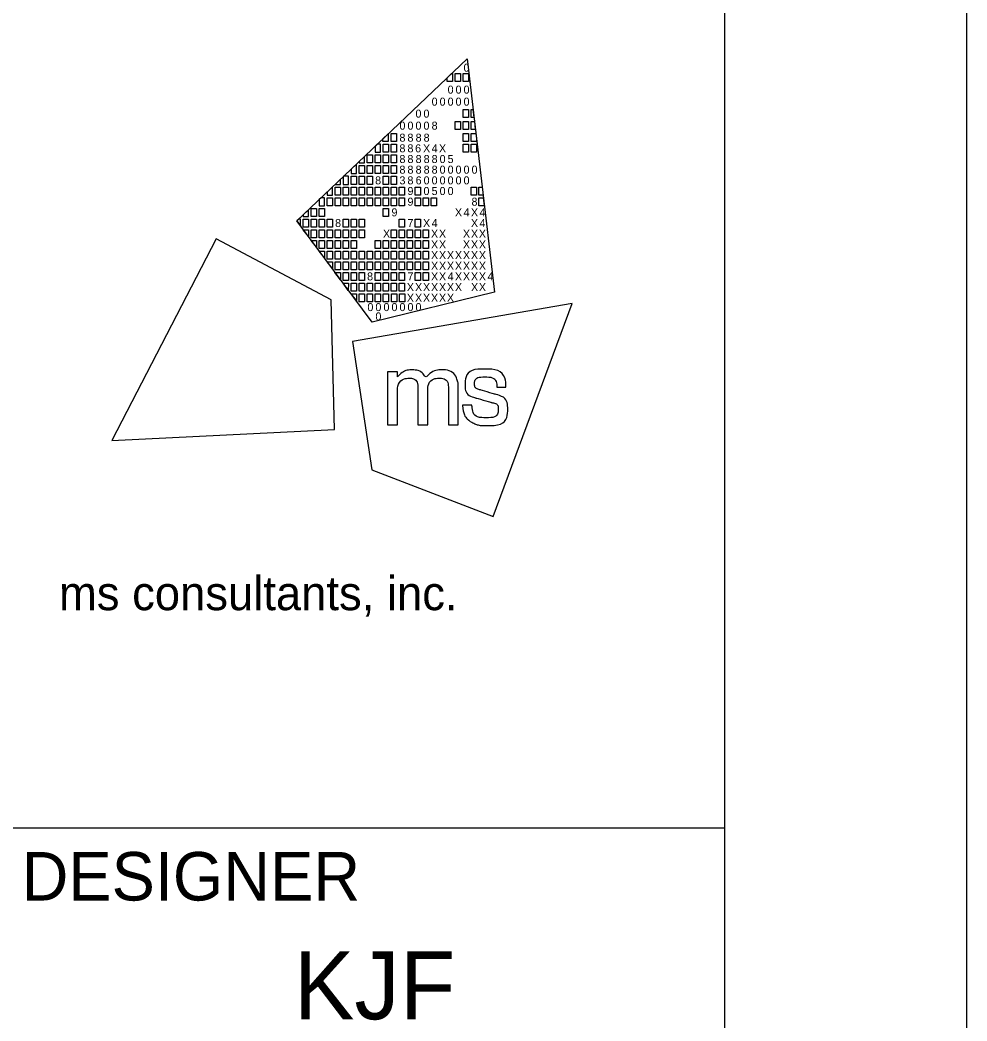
# Model space of a CAD drawing. Extents: x 0 to 40.3, y -1.2 to 22.
# Drawn here: x 32.047 to 34, y 2.102 to 4.166 of the extents above; entities that cross this region are included whole.
import ezdxf

# ---------------------------------------------------------------- set-up
doc = ezdxf.new("R2010")
doc.units = 0
for name, color, linetype in [('SH_Border', 7, 'Continuous'), ('SH_Cut_Line', 7, 'Continuous'), ('SH_Data', 7, 'Continuous')]:
    doc.layers.add(name, color=color, linetype=linetype)

msp = doc.modelspace()

# ---------------------------------------------------------------- linework, layer by layer
at = {"layer": 'SH_Border'}
for p, q in [((32.6175, 3.7519), (32.9688, 4.0861)), ((32.9688, 4.0861), (32.9688, 4.0861)), ((32.9688, 4.0861), (33.0253, 3.6052)), ((32.773, 3.543), (32.6175, 3.7519)), ((33.0253, 3.6052), (32.773, 3.543)), ((32, 2.5), (33.5, 2.5))]:
    msp.add_line(p, q, dxfattribs=at)
for points in [[(1.5, 21.5), (33.5, 21.5), (33.5, 0.5), (1.5, 0.5)], [(32.9279, 4.0472), (32.9369, 4.0558), (32.9389, 4.0558), (32.9389, 4.0393), (32.9279, 4.0393)], [(32.9444, 4.0558), (32.9554, 4.0558), (32.9554, 4.0393), (32.9444, 4.0393)], [(32.9609, 4.0558), (32.9719, 4.0558), (32.9719, 4.0393), (32.9609, 4.0393)], [(32.9606, 3.9815), (32.9716, 3.9815), (32.9716, 3.965), (32.9606, 3.965)], [(32.9771, 3.9815), (32.9811, 3.9815), (32.983, 3.965), (32.9771, 3.965)], [(32.9441, 3.9567), (32.9551, 3.9567), (32.9551, 3.9402), (32.9441, 3.9402)], [(32.9606, 3.9567), (32.9716, 3.9567), (32.9716, 3.9402), (32.9606, 3.9402)], [(32.9771, 3.9567), (32.984, 3.9567), (32.9859, 3.9402), (32.9771, 3.9402)], [(32.7953, 3.9211), (32.8064, 3.9316), (32.8064, 3.9154), (32.7953, 3.9154)], [(32.8123, 3.9319), (32.8233, 3.9319), (32.8233, 3.9154), (32.8123, 3.9154)], [(32.9606, 3.9319), (32.9716, 3.9319), (32.9716, 3.9154), (32.9606, 3.9154)], [(32.9771, 3.9319), (32.9869, 3.9319), (32.9881, 3.9218), (32.9881, 3.9154), (32.9771, 3.9154)], [(32.7958, 3.9099), (32.8068, 3.9099), (32.8068, 3.8934), (32.7958, 3.8934)], [(32.8123, 3.9099), (32.8233, 3.9099), (32.8233, 3.8934), (32.8123, 3.8934)], [(32.9606, 3.9099), (32.9716, 3.9099), (32.9716, 3.8934), (32.9606, 3.8934)], [(32.9771, 3.9099), (32.9881, 3.9099), (32.9881, 3.8934), (32.9771, 3.8934)], [(32.7627, 3.8879), (32.7737, 3.8879), (32.7737, 3.8714), (32.7627, 3.8714)], [(32.7793, 3.8879), (32.7903, 3.8879), (32.7903, 3.8714), (32.7793, 3.8714)], [(32.7958, 3.8879), (32.8068, 3.8879), (32.8068, 3.8714), (32.7958, 3.8714)], [(32.8123, 3.8879), (32.8233, 3.8879), (32.8233, 3.8714), (32.8123, 3.8714)], [(32.7462, 3.8659), (32.7572, 3.8659), (32.7572, 3.8494), (32.7462, 3.8494)], [(32.7627, 3.8659), (32.7737, 3.8659), (32.7737, 3.8494), (32.7627, 3.8494)], [(32.7793, 3.8659), (32.7903, 3.8659), (32.7903, 3.8494), (32.7793, 3.8494)], [(32.7958, 3.8659), (32.8068, 3.8659), (32.8068, 3.8494), (32.7958, 3.8494)], [(32.8123, 3.8659), (32.8233, 3.8659), (32.8233, 3.8494), (32.8123, 3.8494)], [(32.7297, 3.8439), (32.7407, 3.8439), (32.7407, 3.8273), (32.7297, 3.8273)], [(32.7462, 3.8439), (32.7572, 3.8439), (32.7572, 3.8273), (32.7462, 3.8273)], [(32.7627, 3.8439), (32.7737, 3.8439), (32.7737, 3.8273), (32.7627, 3.8273)], [(32.7958, 3.8439), (32.8068, 3.8439), (32.8068, 3.8273), (32.7958, 3.8273)], [(32.8123, 3.8439), (32.8233, 3.8439), (32.8233, 3.8273), (32.8123, 3.8273)], [(32.6967, 3.8218), (32.7077, 3.8218), (32.7077, 3.8053), (32.6967, 3.8053)], [(32.7132, 3.8218), (32.7242, 3.8218), (32.7242, 3.8053), (32.7132, 3.8053)], [(32.7297, 3.8218), (32.7407, 3.8218), (32.7407, 3.8053), (32.7297, 3.8053)], [(32.7462, 3.8218), (32.7572, 3.8218), (32.7572, 3.8053), (32.7462, 3.8053)], [(32.7627, 3.8218), (32.7737, 3.8218), (32.7737, 3.8053), (32.7627, 3.8053)], [(32.7793, 3.8218), (32.7903, 3.8218), (32.7903, 3.8053), (32.7793, 3.8053)], [(32.7958, 3.8218), (32.8068, 3.8218), (32.8068, 3.8053), (32.7958, 3.8053)], [(32.8123, 3.8218), (32.8233, 3.8218), (32.8233, 3.8053), (32.8123, 3.8053)], [(32.8288, 3.8218), (32.8398, 3.8218), (32.8398, 3.8053), (32.8288, 3.8053)], [(32.8618, 3.8218), (32.8728, 3.8218), (32.8728, 3.8053), (32.8618, 3.8053)], [(32.9771, 3.8218), (32.9881, 3.8218), (32.9881, 3.8053), (32.9771, 3.8053)], [(32.9935, 3.8218), (32.9998, 3.8218), (33.0018, 3.8053), (32.9935, 3.8053)], [(32.6802, 3.7998), (32.6912, 3.7998), (32.6912, 3.7833), (32.6802, 3.7833)], [(32.6967, 3.7998), (32.7077, 3.7998), (32.7077, 3.7833), (32.6967, 3.7833)], [(32.7132, 3.7998), (32.7242, 3.7998), (32.7242, 3.7833), (32.7132, 3.7833)], [(32.7297, 3.7998), (32.7407, 3.7998), (32.7407, 3.7833), (32.7297, 3.7833)], [(32.7462, 3.7998), (32.7572, 3.7998), (32.7572, 3.7833), (32.7462, 3.7833)], [(32.7627, 3.7998), (32.7737, 3.7998), (32.7737, 3.7833), (32.7627, 3.7833)], [(32.7793, 3.7998), (32.7903, 3.7998), (32.7903, 3.7833), (32.7793, 3.7833)], [(32.7958, 3.7998), (32.8068, 3.7998), (32.8068, 3.7833), (32.7958, 3.7833)], [(32.8123, 3.7998), (32.8233, 3.7998), (32.8233, 3.7833), (32.8123, 3.7833)], [(32.8288, 3.7998), (32.8398, 3.7998), (32.8398, 3.7833), (32.8288, 3.7833)], [(32.8618, 3.7998), (32.8728, 3.7998), (32.8728, 3.7833), (32.8618, 3.7833)], [(32.8783, 3.7998), (32.8893, 3.7998), (32.8893, 3.7833), (32.8783, 3.7833)], [(32.8947, 3.7998), (32.9057, 3.7998), (32.9057, 3.7833), (32.8947, 3.7833)], [(32.9935, 3.7998), (33.0024, 3.7998), (33.0044, 3.7833), (32.9935, 3.7833)], [(32.6471, 3.7778), (32.6581, 3.7778), (32.6581, 3.7613), (32.6471, 3.7613)], [(32.6637, 3.7778), (32.6747, 3.7778), (32.6747, 3.7613), (32.6637, 3.7613)], [(32.7958, 3.7778), (32.8068, 3.7778), (32.8068, 3.7613), (32.7958, 3.7613)], [(32.6306, 3.7558), (32.6416, 3.7558), (32.6416, 3.7393), (32.6306, 3.7393)], [(32.6471, 3.7558), (32.6581, 3.7558), (32.6581, 3.7393), (32.6471, 3.7393)], [(32.6637, 3.7558), (32.6747, 3.7558), (32.6747, 3.7393), (32.6637, 3.7393)], [(32.6802, 3.7558), (32.6912, 3.7558), (32.6912, 3.7393), (32.6802, 3.7393)], [(32.7132, 3.7558), (32.7242, 3.7558), (32.7242, 3.7393), (32.7132, 3.7393)], [(32.7297, 3.7558), (32.7407, 3.7558), (32.7407, 3.7393), (32.7297, 3.7393)], [(32.7462, 3.7558), (32.7572, 3.7558), (32.7572, 3.7393), (32.7462, 3.7393)], [(32.8288, 3.7558), (32.8398, 3.7558), (32.8398, 3.7393), (32.8288, 3.7393)], [(32.8618, 3.7558), (32.8728, 3.7558), (32.8728, 3.7393), (32.8618, 3.7393)], [(32.6306, 3.7338), (32.6416, 3.7338), (32.6416, 3.72)], [(32.6471, 3.7338), (32.6581, 3.7338), (32.6581, 3.7173), (32.6471, 3.7173)], [(32.6637, 3.7338), (32.6747, 3.7338), (32.6747, 3.7173), (32.6637, 3.7173)], [(32.6802, 3.7338), (32.6912, 3.7338), (32.6912, 3.7173), (32.6802, 3.7173)], [(32.6967, 3.7338), (32.7077, 3.7338), (32.7077, 3.7173), (32.6967, 3.7173)], [(32.7132, 3.7338), (32.7242, 3.7338), (32.7242, 3.7173), (32.7132, 3.7173)], [(32.7297, 3.7338), (32.7407, 3.7338), (32.7407, 3.7173), (32.7297, 3.7173)], [(32.7462, 3.7338), (32.7572, 3.7338), (32.7572, 3.7173), (32.7462, 3.7173)], [(32.8123, 3.7338), (32.8233, 3.7338), (32.8233, 3.7173), (32.8123, 3.7173)], [(32.8288, 3.7338), (32.8398, 3.7338), (32.8398, 3.7173), (32.8288, 3.7173)], [(32.8453, 3.7338), (32.8563, 3.7338), (32.8563, 3.7173), (32.8453, 3.7173)], [(32.8618, 3.7338), (32.8728, 3.7338), (32.8728, 3.7173), (32.8618, 3.7173)], [(32.8783, 3.7338), (32.8893, 3.7338), (32.8893, 3.7173), (32.8783, 3.7173)], [(32.6471, 3.7117), (32.6581, 3.7117), (32.6581, 3.698)], [(32.6637, 3.7117), (32.6747, 3.7117), (32.6747, 3.6952), (32.6637, 3.6952)], [(32.6802, 3.7117), (32.6912, 3.7117), (32.6912, 3.6952), (32.6802, 3.6952)], [(32.6967, 3.7117), (32.7077, 3.7117), (32.7077, 3.6952), (32.6967, 3.6952)], [(32.7132, 3.7117), (32.7242, 3.7117), (32.7242, 3.6952), (32.7132, 3.6952)], [(32.7297, 3.7117), (32.7407, 3.7117), (32.7407, 3.6952), (32.7297, 3.6952)], [(32.7793, 3.7117), (32.7903, 3.7117), (32.7903, 3.6952), (32.7793, 3.6952)], [(32.7958, 3.7117), (32.8068, 3.7117), (32.8068, 3.6952), (32.7958, 3.6952)], [(32.8123, 3.7117), (32.8233, 3.7117), (32.8233, 3.6952), (32.8123, 3.6952)], [(32.8288, 3.7117), (32.8398, 3.7117), (32.8398, 3.6952), (32.8288, 3.6952)], [(32.8453, 3.7117), (32.8563, 3.7117), (32.8563, 3.6952), (32.8453, 3.6952)], [(32.8618, 3.7117), (32.8728, 3.7117), (32.8728, 3.6952), (32.8618, 3.6952)], [(32.8783, 3.7117), (32.8893, 3.7117), (32.8893, 3.6952), (32.8783, 3.6952)], [(32.6637, 3.6897), (32.6747, 3.6897), (32.6747, 3.676)], [(32.6747, 3.6897), (32.6747, 3.6897), (32.6747, 3.6897)], [(32.6802, 3.6897), (32.6912, 3.6897), (32.6912, 3.6732), (32.6802, 3.6732)], [(32.6967, 3.6897), (32.7077, 3.6897), (32.7077, 3.6732), (32.6967, 3.6732)], [(32.7132, 3.6897), (32.7242, 3.6897), (32.7242, 3.6732), (32.7132, 3.6732)], [(32.7297, 3.6897), (32.7407, 3.6897), (32.7407, 3.6732), (32.7297, 3.6732)], [(32.7462, 3.6897), (32.7572, 3.6897), (32.7572, 3.6732), (32.7462, 3.6732)], [(32.7627, 3.6897), (32.7737, 3.6897), (32.7737, 3.6732), (32.7627, 3.6732)], [(32.7793, 3.6897), (32.7903, 3.6897), (32.7903, 3.6732), (32.7793, 3.6732)], [(32.7958, 3.6897), (32.8068, 3.6897), (32.8068, 3.6732), (32.7958, 3.6732)], [(32.8123, 3.6897), (32.8233, 3.6897), (32.8233, 3.6732), (32.8123, 3.6732)], [(32.8288, 3.6897), (32.8398, 3.6897), (32.8398, 3.6732), (32.8288, 3.6732)], [(32.8453, 3.6897), (32.8563, 3.6897), (32.8563, 3.6732), (32.8453, 3.6732)], [(32.8618, 3.6897), (32.8728, 3.6897), (32.8728, 3.6732), (32.8618, 3.6732)], [(32.8783, 3.6897), (32.8893, 3.6897), (32.8893, 3.6732), (32.8783, 3.6732)], [(32.6802, 3.6677), (32.6912, 3.6677), (32.6912, 3.654)], [(32.6967, 3.6677), (32.7077, 3.6677), (32.7077, 3.6512), (32.6967, 3.6512)], [(32.7132, 3.6677), (32.7242, 3.6677), (32.7242, 3.6512), (32.7132, 3.6512)], [(32.7297, 3.6677), (32.7407, 3.6677), (32.7407, 3.6512), (32.7297, 3.6512)], [(32.7462, 3.6677), (32.7572, 3.6677), (32.7572, 3.6512), (32.7462, 3.6512)], [(32.7627, 3.6677), (32.7737, 3.6677), (32.7737, 3.6512), (32.7627, 3.6512)], [(32.7793, 3.6677), (32.7903, 3.6677), (32.7903, 3.6512), (32.7793, 3.6512)], [(32.7958, 3.6677), (32.8068, 3.6677), (32.8068, 3.6512), (32.7958, 3.6512)], [(32.8123, 3.6677), (32.8233, 3.6677), (32.8233, 3.6512), (32.8123, 3.6512)], [(32.8288, 3.6677), (32.8398, 3.6677), (32.8398, 3.6512), (32.8288, 3.6512)], [(32.8453, 3.6677), (32.8563, 3.6677), (32.8563, 3.6512), (32.8453, 3.6512)], [(32.8618, 3.6677), (32.8728, 3.6677), (32.8728, 3.6512), (32.8618, 3.6512)], [(32.8783, 3.6677), (32.8893, 3.6677), (32.8893, 3.6512), (32.8783, 3.6512)], [(32.7077, 3.6305), (32.6965, 3.6457), (32.7077, 3.6457)], [(32.7132, 3.6457), (32.7242, 3.6457), (32.7242, 3.6292), (32.7132, 3.6292)], [(32.7297, 3.6457), (32.7407, 3.6457), (32.7407, 3.6292), (32.7297, 3.6292)], [(32.7462, 3.6457), (32.7572, 3.6457), (32.7572, 3.6292), (32.7462, 3.6292)], [(32.7793, 3.6457), (32.7903, 3.6457), (32.7903, 3.6292), (32.7793, 3.6292)], [(32.7958, 3.6457), (32.8068, 3.6457), (32.8068, 3.6292), (32.7958, 3.6292)], [(32.8123, 3.6457), (32.8233, 3.6457), (32.8233, 3.6292), (32.8123, 3.6292)], [(32.8288, 3.6457), (32.8398, 3.6457), (32.8398, 3.6292), (32.8288, 3.6292)], [(32.8618, 3.6457), (32.8728, 3.6457), (32.8728, 3.6292), (32.8618, 3.6292)], [(32.8783, 3.6457), (32.8893, 3.6457), (32.8893, 3.6292), (32.8783, 3.6292)], [(32.724, 3.6082), (32.7132, 3.6237), (32.7242, 3.6237)], [(32.7297, 3.6237), (32.7407, 3.6237), (32.7407, 3.6072), (32.7297, 3.6072)], [(32.7462, 3.6237), (32.7572, 3.6237), (32.7572, 3.6072), (32.7462, 3.6072)], [(32.7627, 3.6237), (32.7737, 3.6237), (32.7737, 3.6072), (32.7627, 3.6072)], [(32.7793, 3.6237), (32.7903, 3.6237), (32.7903, 3.6072), (32.7793, 3.6072)], [(32.7958, 3.6237), (32.8068, 3.6237), (32.8068, 3.6072), (32.7958, 3.6072)], [(32.8123, 3.6237), (32.8233, 3.6237), (32.8233, 3.6072), (32.8123, 3.6072)], [(32.8288, 3.6237), (32.8398, 3.6237), (32.8398, 3.6072), (32.8288, 3.6072)], [(32.7302, 3.6017), (32.7407, 3.6017), (32.7408, 3.5875)], [(32.7463, 3.6017), (32.7573, 3.6017), (32.7573, 3.5852), (32.7463, 3.5852)], [(32.763, 3.6017), (32.774, 3.6017), (32.774, 3.5852), (32.763, 3.5852)], [(32.7794, 3.6017), (32.7904, 3.6017), (32.7904, 3.5852), (32.7794, 3.5852)], [(32.796, 3.6017), (32.807, 3.6017), (32.807, 3.5852), (32.796, 3.5852)], [(32.8129, 3.6017), (32.8239, 3.6017), (32.8239, 3.5851), (32.8129, 3.5851)], [(32.8296, 3.6017), (32.8406, 3.6017), (32.8406, 3.5851), (32.8296, 3.5851)]]:
    msp.add_lwpolyline(points, close=True, dxfattribs=at)
for points in [[(32.7903, 3.9099), (32.7836, 3.9099), (32.7793, 3.9058), (32.7793, 3.8934), (32.7903, 3.8934), (32.7903, 3.9099)], [(32.7572, 3.8849), (32.7462, 3.8744), (32.7462, 3.8714), (32.7572, 3.8714), (32.7572, 3.8849)], [(32.7407, 3.8691), (32.7297, 3.8587), (32.7297, 3.8494), (32.7407, 3.8494), (32.7407, 3.8691)], [(32.7242, 3.8439), (32.7141, 3.8439), (32.7132, 3.843), (32.7132, 3.8273), (32.7242, 3.8273), (32.7242, 3.8439)], [(32.6912, 3.822), (32.6802, 3.8115), (32.6802, 3.8053), (32.6912, 3.8053), (32.6912, 3.822)], [(32.7077, 3.8377), (32.6968, 3.8273), (32.7077, 3.8273), (32.7077, 3.8377)], [(32.6747, 3.7998), (32.6679, 3.7998), (32.6637, 3.7958), (32.6637, 3.7833), (32.6747, 3.7833), (32.6747, 3.7998)], [(32.6416, 3.7749), (32.6306, 3.7644), (32.6306, 3.7613), (32.6416, 3.7613), (32.6416, 3.7749)], [(32.6251, 3.7558), (32.6216, 3.7558), (32.6175, 3.7519), (32.6251, 3.7417), (32.6251, 3.7558)], [(32.4512, 3.7149), (32.2359, 3.2988), (32.6956, 3.3215), (32.6884, 3.5892), (32.4512, 3.7149)], [(33.0229, 3.1422), (33.1859, 3.5814), (32.7324, 3.5029), (32.7722, 3.2381), (33.0229, 3.1422)]]:
    msp.add_lwpolyline(points, dxfattribs=at)
for points in [[(32.8048, 3.3315), (32.8048, 3.3315), (32.8048, 3.4409), (32.8048, 3.4409), (32.8048, 3.4409), (32.8255, 3.4409), (32.8255, 3.4409), (32.8255, 3.4409), (32.8255, 3.4297), (32.8255, 3.4297), (32.8346, 3.4399), (32.8457, 3.4445), (32.8555, 3.4445), (32.8688, 3.4445), (32.8791, 3.4372), (32.8837, 3.4266), (32.8915, 3.4381), (32.905, 3.4446), (32.9166, 3.4446), (32.9325, 3.4446), (32.9451, 3.435), (32.9494, 3.4213), (32.9494, 3.4212), (32.9494, 3.4212), (32.9494, 3.4212), (32.9501, 3.419), (32.9506, 3.4172), (32.9506, 3.4071), (32.9506, 3.4071), (32.9506, 3.3314), (32.9506, 3.3314), (32.9506, 3.3314), (32.9303, 3.3314), (32.9303, 3.3314), (32.9303, 3.3314), (32.9303, 3.4048), (32.9303, 3.4048), (32.9303, 3.4201), (32.9219, 3.4274), (32.911, 3.4274), (32.8995, 3.4274), (32.8879, 3.4171), (32.8879, 3.4001), (32.8879, 3.4001), (32.8879, 3.3315), (32.8879, 3.3315), (32.8879, 3.3315), (32.8674, 3.3315), (32.8674, 3.3315), (32.8674, 3.3315), (32.8674, 3.4059), (32.8674, 3.4059), (32.8674, 3.4203), (32.8588, 3.4274), (32.8496, 3.4274), (32.8384, 3.4274), (32.8254, 3.417), (32.8254, 3.3962), (32.8254, 3.3962), (32.8254, 3.3315), (32.8254, 3.3315), (32.8254, 3.3315), (32.8048, 3.3315), (32.8048, 3.3315)], [(32.9595, 3.3709), (32.9595, 3.3709), (32.9595, 3.3717), (32.9595, 3.3717), (32.9595, 3.3717), (32.9603, 3.3717), (32.9603, 3.3717), (32.9603, 3.3717), (32.9783, 3.3717), (32.9783, 3.3717), (32.9783, 3.3717), (32.9789, 3.3717), (32.9789, 3.3717), (32.9789, 3.3717), (32.979, 3.371), (32.979, 3.371), (32.9803, 3.3554), (32.9887, 3.346), (33.009, 3.346), (33.0273, 3.346), (33.0333, 3.3554), (33.0333, 3.3631), (33.0333, 3.3732), (33.0256, 3.3758), (33.0175, 3.378), (33.0175, 3.378), (32.987, 3.3867), (32.987, 3.3867), (32.972, 3.3909), (32.9648, 3.4019), (32.9648, 3.4142), (32.9648, 3.4303), (32.9768, 3.4462), (33.0052, 3.4462), (33.0348, 3.4462), (33.0489, 3.4285), (33.0489, 3.4095), (33.0489, 3.4095), (33.0489, 3.4087), (33.0489, 3.4087), (33.0489, 3.4087), (33.0482, 3.4087), (33.0482, 3.4087), (33.0482, 3.4087), (33.0312, 3.4087), (33.0312, 3.4087), (33.0312, 3.4087), (33.0305, 3.4087), (33.0305, 3.4087), (33.0305, 3.4087), (33.0305, 3.4094), (33.0305, 3.4094), (33.0301, 3.4208), (33.0226, 3.43), (33.0056, 3.43), (32.9891, 3.43), (32.9843, 3.4218), (32.9843, 3.4157), (32.9843, 3.4108), (32.9869, 3.4059), (32.9959, 3.4033), (32.9959, 3.4033), (33.0255, 3.3948), (33.0255, 3.3948), (33.0462, 3.3889), (33.0527, 3.3777), (33.0527, 3.3639), (33.0527, 3.3462), (33.041, 3.3298), (33.0087, 3.3298), (32.9952, 3.3298), (32.9877, 3.3321), (32.9823, 3.3348), (32.969, 3.3414), (32.9609, 3.3536), (32.9595, 3.3709)]]:
    msp.add_open_spline(points, degree=3, dxfattribs=at)
at = {"layer": 'SH_Cut_Line'}
msp.add_lwpolyline([(0, 0), (34, 0), (34, 22), (0, 22)], close=True, dxfattribs=at)
at = {"layer": 'SH_Data'}
msp.add_line((32.75, 3.5), (32.75, 3.5), dxfattribs=at)

# ---------------------------------------------------------------- texts
at = {"layer": 'SH_Border'}
for s, height, p in [('0', 0.0165, (32.9617, 4.0597)), ('0', 0.0165, (32.9288, 4.0145)), ('0', 0.0165, (32.9452, 4.0145)), ('0', 0.0165, (32.9617, 4.0145)), ('0', 0.0165, (32.8958, 3.9897)), ('0', 0.0165, (32.9123, 3.9897)), ('0', 0.0165, (32.9288, 3.9897)), ('0', 0.0165, (32.9452, 3.9897)), ('0', 0.0165, (32.9617, 3.9897)), ('0', 0.0165, (32.8625, 3.965)), ('0', 0.0165, (32.879, 3.965)), ('0', 0.0165, (32.8295, 3.9402)), ('0', 0.0165, (32.846, 3.9402)), ('0', 0.0165, (32.8625, 3.9402)), ('0', 0.0165, (32.879, 3.9402)), ('8', 0.0165, (32.8958, 3.9402)), ('8', 0.0165, (32.8295, 3.9154)), ('8', 0.0165, (32.846, 3.9154)), ('8', 0.0165, (32.8628, 3.9154)), ('8', 0.0165, (32.8793, 3.9154)), ('8', 0.0165, (32.8295, 3.8934)), ('8', 0.0165, (32.846, 3.8934)), ('6', 0.0165, (32.8618, 3.8934)), ('X', 0.0165, (32.8781, 3.8934)), ('4', 0.0165, (32.8958, 3.8934)), ('X', 0.0165, (32.911, 3.8934)), ('8', 0.0165, (32.8295, 3.8713)), ('8', 0.0165, (32.846, 3.8713)), ('8', 0.0165, (32.8628, 3.8713)), ('8', 0.0165, (32.8794, 3.8713)), ('8', 0.0165, (32.8958, 3.8713)), ('0', 0.0165, (32.9123, 3.8713)), ('5', 0.0165, (32.9287, 3.8713)), ('8', 0.0165, (32.8295, 3.8494)), ('8', 0.0165, (32.846, 3.8494)), ('8', 0.0165, (32.8628, 3.8494)), ('8', 0.0165, (32.8794, 3.8494)), ('8', 0.0165, (32.8958, 3.8494)), ('0', 0.0165, (32.9123, 3.8494)), ('0', 0.0165, (32.9288, 3.8494)), ('0', 0.0165, (32.9452, 3.8494)), ('0', 0.0165, (32.9617, 3.8494)), ('0', 0.0165, (32.9782, 3.8494)), ('8', 0.0165, (32.7793, 3.8273)), ('3', 0.0165, (32.8295, 3.8273)), ('8', 0.0165, (32.846, 3.8273)), ('6', 0.0165, (32.8629, 3.8273)), ('0', 0.0165, (32.8793, 3.8273)), ('0', 0.0165, (32.8958, 3.8273)), ('0', 0.0165, (32.9123, 3.8273)), ('0', 0.0165, (32.9288, 3.8273)), ('0', 0.0165, (32.9452, 3.8273)), ('0', 0.0165, (32.9617, 3.8273)), ('9', 0.0165, (32.846, 3.8053)), ('0', 0.0165, (32.879, 3.8053)), ('5', 0.0165, (32.8957, 3.8053)), ('0', 0.0165, (32.9123, 3.8053)), ('0', 0.0165, (32.9288, 3.8053)), ('9', 0.0165, (32.846, 3.7833)), ('8', 0.0165, (32.9781, 3.7833)), ('9', 0.0165, (32.813, 3.7613)), ('X', 0.0165, (32.9439, 3.7613)), ('4', 0.0165, (32.9617, 3.7613)), ('X', 0.0165, (32.9769, 3.7613)), ('4', 0.0165, (32.9946, 3.7613)), ('8', 0.0165, (32.6967, 3.7393)), ('7', 0.0165, (32.846, 3.7393)), ('X', 0.0165, (32.8781, 3.7393)), ('4', 0.0165, (32.8958, 3.7393)), ('X', 0.0165, (32.9769, 3.7393)), ('4', 0.0165, (32.9946, 3.7393)), ('X', 0.0165, (32.7955, 3.7173)), ('X', 0.0165, (32.8945, 3.7173)), ('X', 0.0165, (32.911, 3.7173)), ('X', 0.0165, (32.9604, 3.7173)), ('X', 0.0165, (32.9769, 3.7173)), ('X', 0.0165, (32.9933, 3.7173)), ('X', 0.0165, (32.8945, 3.6952)), ('X', 0.0165, (32.911, 3.6952)), ('X', 0.0165, (32.9604, 3.6952)), ('X', 0.0165, (32.9769, 3.6952)), ('X', 0.0165, (32.9933, 3.6952)), ('X', 0.0165, (32.8945, 3.6732)), ('X', 0.0165, (32.911, 3.6732)), ('X', 0.0165, (32.9274, 3.6732)), ('X', 0.0165, (32.9439, 3.6732)), ('X', 0.0165, (32.9604, 3.6732)), ('X', 0.0165, (32.9769, 3.6732)), ('X', 0.0165, (32.9933, 3.6732)), ('X', 0.0165, (32.8945, 3.6512)), ('X', 0.0165, (32.911, 3.6512)), ('X', 0.0165, (32.9274, 3.6512)), ('X', 0.0165, (32.9439, 3.6512)), ('X', 0.0165, (32.9604, 3.6512)), ('X', 0.0165, (32.9769, 3.6512)), ('X', 0.0165, (32.9933, 3.6512)), ('8', 0.0165, (32.7627, 3.6292)), ('7', 0.0165, (32.846, 3.6292)), ('X', 0.0165, (32.8945, 3.6292)), ('X', 0.0165, (32.911, 3.6292)), ('4', 0.0165, (32.9288, 3.6292)), ('X', 0.0165, (32.9439, 3.6292)), ('X', 0.0165, (32.9604, 3.6292)), ('X', 0.0165, (32.9769, 3.6292)), ('X', 0.0165, (32.9933, 3.6292)), ('4', 0.0165, (33.0111, 3.6292)), ('X', 0.0165, (32.8447, 3.6072)), ('X', 0.0165, (32.8616, 3.6072)), ('X', 0.0165, (32.878, 3.6072)), ('X', 0.0165, (32.8945, 3.6072)), ('X', 0.0165, (32.911, 3.6072)), ('X', 0.0165, (32.9274, 3.6072)), ('X', 0.0165, (32.9439, 3.6072)), ('X', 0.0165, (32.9771, 3.6072)), ('X', 0.0165, (32.9933, 3.6072)), ('X', 0.0165, (32.8447, 3.5851)), ('X', 0.0165, (32.8616, 3.5851)), ('X', 0.0165, (32.878, 3.5851)), ('X', 0.0165, (32.8945, 3.5851)), ('X', 0.0165, (32.911, 3.5851)), ('X', 0.0165, (32.9274, 3.5851)), ('0', 0.0165, (32.7634, 3.5659)), ('0', 0.0165, (32.7799, 3.5659)), ('0', 0.0165, (32.7965, 3.5659)), ('0', 0.0165, (32.813, 3.5659)), ('0', 0.0165, (32.8295, 3.5659)), ('0', 0.0165, (32.846, 3.5659)), ('0', 0.0165, (32.8625, 3.5659)), ('0', 0.0165, (32.7799, 3.5467)), ('ms consultants, inc.', 0.07, (32.1273, 2.9489))]:
    msp.add_text(s, height=height, rotation=360, dxfattribs=at).set_placement(p)
at = {"layer": 'SH_Data'}
for s, height, p in [('DESIGNER', 0.1, (32.05, 2.35)), ('KJF', 0.14, (32.6116, 2.105))]:
    msp.add_text(s, height=height, dxfattribs=at).set_placement(p)

doc.saveas('drawing.dxf')
